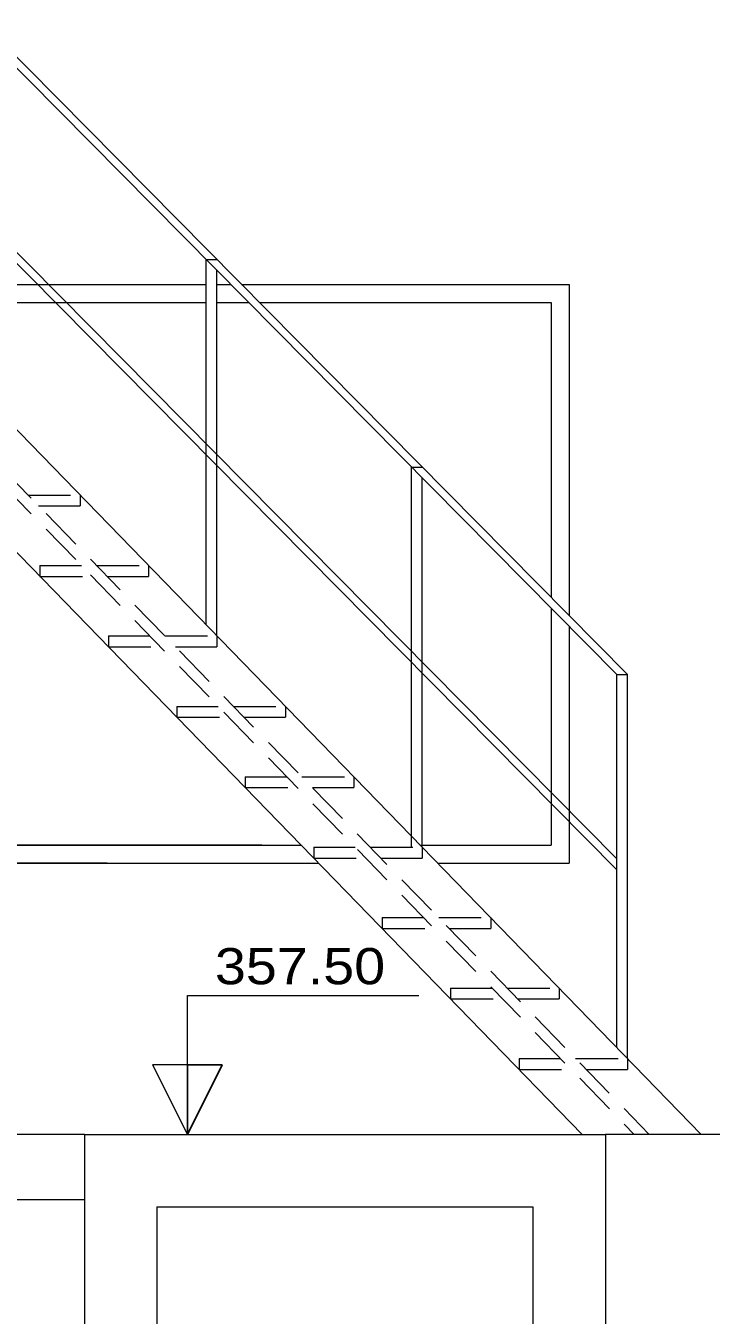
# Model space of a CAD drawing. Extents: x -4160 to -2690, y -474 to 714.
# Drawn here: x -3617.5 to -3590.4, y -333.7 to -282.8 of the extents above; entities that cross this region are included whole.
import ezdxf
from ezdxf.enums import TextEntityAlignment as Align

# ---------------------------------------------------------------- set-up
doc = ezdxf.new("R2010")
doc.units = 0
doc.header["$LTSCALE"] = 0.56
doc.linetypes.add('MEDIUM_DASHED', pattern=[4.5, 3, -1.5])
for name, color, linetype, lineweight in [('10', 7, 'Continuous', 35), ('11', 7, 'Continuous', 13), ('13', 7, 'Continuous', 13), ('19', 7, 'MEDIUM_DASHED', 13), ('2', 7, 'Continuous', 25), ('20', 7, 'Continuous', 13), ('23', 7, 'Continuous', 13), ('63', 7, 'Continuous', 13)]:
    doc.layers.add(name, color=color, linetype=linetype, lineweight=lineweight)

msp = doc.modelspace()

# ---------------------------------------------------------------- linework, layer by layer
at = {"layer": '10', "lineweight": 13}
for p, q in [((-3651.4113, -250.077), (-3593.7271, -308.4155)), ((-3610.3685, -292.0169), (-3609.9399, -292.0169)), ((-3602.2628, -300.2155), (-3601.8342, -300.2155)), ((-3602.2628, -314.7912), (-3602.2628, -300.2155)), ((-3601.8342, -315.2312), (-3601.8342, -300.6484)), ((-3612.6428, -304.1055), (-3612.6428, -304.5341)), ((-3594.1556, -323.1355), (-3594.1556, -308.4141)), ((-3594.1556, -308.4141), (-3593.7271, -308.4141)), ((-3593.7271, -323.5769), (-3593.7271, -308.4155))]:
    msp.add_line(p, q, dxfattribs=at)
at = {"layer": '11'}
for p, q in [((-3615.1756, -326.5726), (-3594.6042, -326.5726)), ((-3615.1756, -326.5726), (-3615.1756, -335.144)), ((-3594.6042, -326.5726), (-3594.6042, -335.144)), ((-3612.3185, -329.4298), (-3612.3185, -335.144))]:
    msp.add_line(p, q, dxfattribs=at)
msp.add_lwpolyline([(-3612.3185, -329.4298), (-3597.4613, -329.4298), (-3597.4613, -335.144)], dxfattribs=at)
at = {"layer": '13'}
for p, q in [((-3651.8384, -250.077), (-3594.1556, -308.4141)), ((-3654.8756, -254.287), (-3594.1556, -315.6941)), ((-3654.8756, -254.7198), (-3594.1556, -316.1283)), ((-3610.3685, -306.4469), (-3610.3685, -292.0169)), ((-3610.3685, -306.4469), (-3610.3685, -292.0169)), ((-3609.9399, -306.8869), (-3609.9399, -292.4498)), ((-3609.9399, -306.8869), (-3609.9399, -292.4498)), ((-3609.9399, -299.8741), (-3609.9399, -292.4498)), ((-3602.2628, -314.7912), (-3602.2628, -300.2155)), ((-3602.2628, -314.7912), (-3602.2628, -300.2155)), ((-3601.8342, -315.2312), (-3601.8342, -300.6484)), ((-3601.8342, -315.2312), (-3601.8342, -300.6484)), ((-3601.8342, -315.2312), (-3601.8342, -300.6484)), ((-3615.1756, -326.5726), (-3619.8185, -326.5726)), ((-3573.8899, -326.5726), (-3594.6042, -326.5726)), ((-3628.747, -329.144), (-3615.1756, -329.144))]:
    msp.add_line(p, q, dxfattribs=at)
at = {"layer": '19'}
for p, q in [((-3655.3184, -262.287), (-3592.8699, -326.5726)), ((-3655.3184, -262.9027), (-3593.4671, -326.5726)), ((-3602.2628, -315.2312), (-3602.2628, -300.2155)), ((-3616.9813, -301.7526), (-3615.3456, -301.7526)), ((-3616.9285, -304.1055), (-3615.2927, -304.1055)), ((-3616.9285, -304.1055), (-3616.9285, -304.5341)), ((-3616.9285, -304.5341), (-3614.8756, -304.5341)), ((-3614.6956, -304.1055), (-3612.6428, -304.1055)), ((-3614.2785, -304.5341), (-3612.6428, -304.5341)), ((-3614.2256, -306.8869), (-3612.5899, -306.8869)), ((-3614.2256, -306.8869), (-3614.2256, -307.3155)), ((-3614.2256, -307.3155), (-3612.1742, -307.3155)), ((-3611.577, -307.3155), (-3609.9399, -307.3155)), ((-3611.5242, -309.6683), (-3609.8885, -309.6683)), ((-3611.5242, -309.6683), (-3611.5242, -310.0969)), ((-3611.5242, -310.0969), (-3609.4713, -310.0969)), ((-3608.8742, -310.0969), (-3607.2385, -310.0969)), ((-3608.8213, -312.4498), (-3607.1856, -312.4498)), ((-3608.8213, -312.4498), (-3608.8213, -312.8783)), ((-3608.8213, -312.8783), (-3606.7699, -312.8783)), ((-3606.1728, -312.8783), (-3604.5356, -312.8783)), ((-3606.1199, -315.2312), (-3604.4842, -315.2312)), ((-3606.1199, -315.2312), (-3606.1199, -315.6598)), ((-3606.1199, -315.6598), (-3604.067, -315.6598)), ((-3603.4699, -315.6598), (-3601.8342, -315.6598)), ((-3603.417, -318.014), (-3601.7813, -318.014)), ((-3603.417, -318.014), (-3603.417, -318.4426)), ((-3603.417, -318.4426), (-3601.3656, -318.4426)), ((-3600.767, -318.4426), (-3599.1313, -318.4426)), ((-3600.7156, -320.7955), (-3599.0799, -320.7955)), ((-3600.7156, -320.7955), (-3600.7156, -321.224)), ((-3600.7156, -321.224), (-3598.6628, -321.224)), ((-3598.0656, -321.224), (-3596.4299, -321.224)), ((-3598.0128, -323.5769), (-3596.3771, -323.5769)), ((-3598.0128, -323.5769), (-3598.0128, -324.0055)), ((-3598.0128, -324.0055), (-3595.9613, -324.0055)), ((-3595.3628, -324.0055), (-3593.7271, -324.0055))]:
    msp.add_line(p, q, dxfattribs=at)
at = {"layer": '19', "linetype": 'Continuous'}
for p, q in [((-3653.2684, -262.287), (-3590.8171, -326.5726)), ((-3655.3184, -265.017), (-3595.5185, -326.5726))]:
    msp.add_line(p, q, dxfattribs=at)
at = {"layer": '19'}
for points in [[(-3617.397, -301.3241), (-3615.3456, -301.3241), (-3615.3456, -301.7526)], [(-3611.9928, -306.8869), (-3609.9399, -306.8869), (-3609.9399, -307.3155)], [(-3609.2913, -309.6683), (-3607.2385, -309.6683), (-3607.2385, -310.0969)], [(-3606.5885, -312.4498), (-3604.5356, -312.4498), (-3604.5356, -312.8783)], [(-3603.8856, -315.2312), (-3601.8342, -315.2312), (-3601.8342, -315.6598)], [(-3601.1842, -318.014), (-3599.1313, -318.014), (-3599.1313, -318.4426)], [(-3598.4813, -320.7955), (-3596.4299, -320.7955), (-3596.4299, -321.224)], [(-3595.7799, -323.5769), (-3593.7271, -323.5769), (-3593.7271, -324.0055)]]:
    msp.add_lwpolyline(points, dxfattribs=at)
at = {"layer": '2'}
msp.add_line((-3611.1084, -326.5727), (-3609.737, -323.8298), dxfattribs=at)
msp.add_lwpolyline([(-3611.1084, -326.5727), (-3611.1084, -323.8298), (-3609.737, -323.8298)], close=True, dxfattribs=at)
at = {"layer": '20'}
for p, q in [((-3618.047, -293.0012), (-3610.3685, -293.0012)), ((-3609.9399, -293.0012), (-3609.3956, -293.0012)), ((-3608.967, -293.0012), (-3596.0328, -293.0012)), ((-3596.0328, -293.0012), (-3596.0328, -306.0826)), ((-3618.047, -293.7155), (-3610.3685, -293.7155)), ((-3609.9399, -293.7155), (-3608.6899, -293.7155)), ((-3608.2613, -293.7155), (-3596.7471, -293.7155)), ((-3596.7471, -293.7155), (-3596.7471, -305.3598)), ((-3596.7471, -305.7926), (-3596.7471, -315.1441)), ((-3596.0328, -306.5155), (-3596.0328, -315.8583)), ((-3621.8185, -315.1441), (-3606.6213, -315.1441)), ((-3608.1713, -315.1441), (-3618.6456, -315.1441)), ((-3601.9199, -315.1441), (-3596.7471, -315.1441)), ((-3621.8185, -315.8583), (-3605.927, -315.8583)), ((-3614.2713, -315.8583), (-3618.6456, -315.8583)), ((-3601.2256, -315.8583), (-3596.0328, -315.8583))]:
    msp.add_line(p, q, dxfattribs=at)
at = {"layer": '23'}
for p, q in [((-3610.3685, -299.4412), (-3610.3685, -292.0169)), ((-3602.2628, -307.6398), (-3602.2628, -300.2155)), ((-3601.8342, -308.0726), (-3601.8342, -300.6484)), ((-3602.2628, -314.6483), (-3602.2628, -308.0726)), ((-3601.8342, -315.0898), (-3601.8342, -308.5055))]:
    msp.add_line(p, q, dxfattribs=at)
at = {"layer": '63'}
for p, q in [((-3611.1085, -321.0869), (-3601.9656, -321.0869)), ((-3611.1085, -323.8298), (-3611.1085, -321.0869)), ((-3612.4799, -323.8298), (-3611.1085, -326.5726)), ((-3609.737, -323.8298), (-3612.4799, -323.8298)), ((-3611.1085, -326.5726), (-3609.737, -323.8298))]:
    msp.add_line(p, q, dxfattribs=at)

# ---------------------------------------------------------------- texts
at = {"layer": '2', "width": 1.15}
msp.add_text('357.50', height=1.429, dxfattribs=at).set_placement((-3606.6598, -320.6441), align=Align.CENTER)

doc.saveas('drawing.dxf')
